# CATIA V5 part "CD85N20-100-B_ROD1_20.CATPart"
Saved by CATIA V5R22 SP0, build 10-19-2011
Part number: CD85N20-100-B_ROD1_20
Revision: ANY
Definition: UNKNOWN
Nomenclature: CD85N20-100-B_ROD1_20
Source: Unknown
Bounding box of the stored display mesh (mm): x -10 to 10, y -10 to 10, z 0 to 177.5
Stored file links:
  D:\PER\CAO_PER_MODIF_2025\CAO_PER_pick&place_2024P\Sous_Ensemble_Flacon\CD85N20-100-B_ROD1_20.CATPart
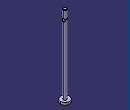
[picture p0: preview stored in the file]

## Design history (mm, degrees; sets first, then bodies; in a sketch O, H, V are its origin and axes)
Body1 "MALE_FLATS" (main body)
  Solid1: solid without history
